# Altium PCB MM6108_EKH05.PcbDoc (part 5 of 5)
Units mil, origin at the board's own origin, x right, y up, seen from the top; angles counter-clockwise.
Board outline 6023.62 x 3425.2 mil, 4 copper layers (Top Layer, Ground Plane, Middle Layer, Bottom Layer), stack 76.15 mil thick; 212 components, 163 nets, 749 pads, 1477 vias.
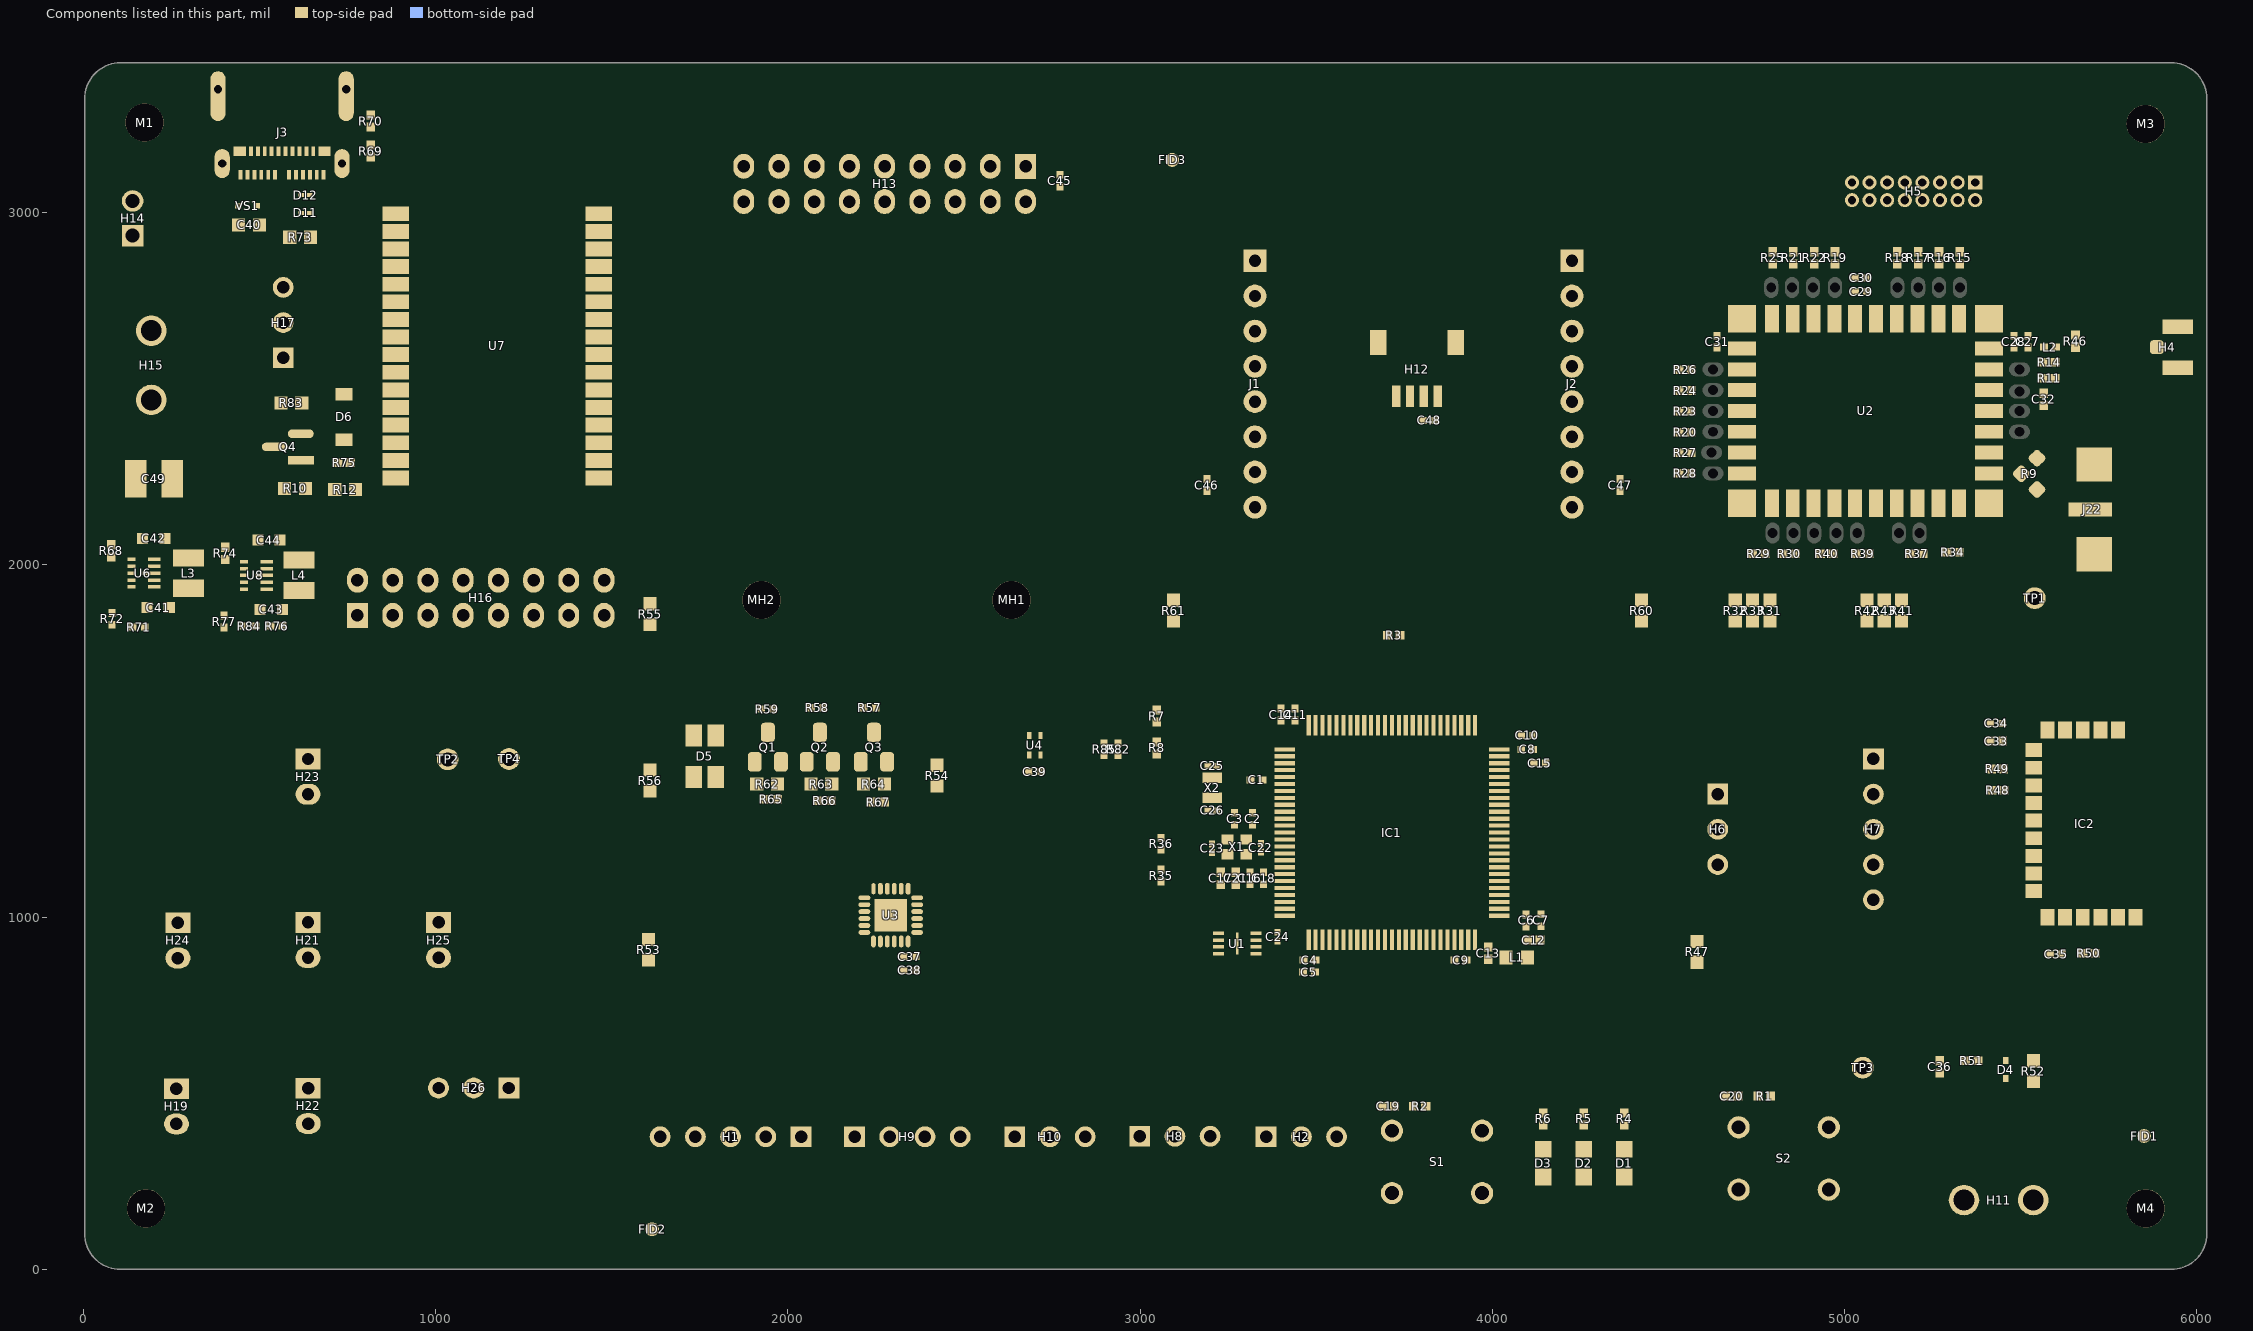
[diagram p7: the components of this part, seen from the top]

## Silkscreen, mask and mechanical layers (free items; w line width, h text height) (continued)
Fab Notes:
  lines w3.94: -58.84,-1054.17 -58.84,-602.42 1478.22,-602.42 1478.22,-1054.62 -58.39,-1054.62 ; 474.62,-1053.22 474.62,-602.42 ; 474.62,-964.17 1479.54,-964.17 ; 474.62,-874.07 1479.54,-874.07 ; 474.62,-783.52 1479.54,-783.52 ; 474.62,-692.97 1479.54,-692.97 ; 1182.3,-1055.61 1182.3,-965.06
  text "NOTES: UNLESS OTHERWISE SPECIFIED0" at -3357.21,2832.86 h60
  text "1. SPECIFICATIONS/TOLERANCES:" at -3357.21,2762.86 h60
  text "A. FABRICATE PER IPC-6012, CLASS 2, USING PROVIDED DATA FILES XXXXXXXX.ZIP" at -3357.21,2692.86 h60
  text "B. ALL SPECIFICATIONS USED SHALL BE PER THEIR LATEST REVISIONS." at -3357.21,2622.86 h60
  text "C. THE DIMENSIONS OF CIRCUIT FEATURES IN THE PROVIDED DATA MAY BE ADJUSTED" at -3357.21,2552.86 h60
  text "ONLY TO COMPENSATE FOR PROCESS TOLERANCES; ADDING, REMOVING OR RELOCATING" at -3357.21,2482.86 h60
  text "CIRCUIT FEATURES IS NOT ALLOWED" at -3357.21,2412.86 h60
  text "D. REMOVE ALL BURRS AND BREAK SHARP EDGES, .381 [.015] MAX RADIUS." at -3357.21,2342.86 h60
  text "E. PARENTHETICAL INFORMATION IS FOR REFERENCE ONLY." at -3357.21,2272.86 h60
  text "F. REPAIR OF PCB DEFECTS IS NOT PERMITTED." at -3357.21,2202.86 h60
  text "2. DIELECTRIC MATERIAL:" at -3357.25,2062.86 h60
  text "A. DIELECTRIC MATERIAL SHALL BE PER IPC-4101/99, /124, /126 OR /129 (RoHS COMPLIANT EPOXY-GLASS)" at -3357.21,1992.86 h60
  text "B. MINIMUM DIELECTRIC THICKNESS SHALL BE .051 [.002] FOR REFERENCED STACK-UP" at -3357.21,1922.86 h60
  text "DIMENSIONS OF.076 [.003] OR GREATER; IPC-6012 REQUIREMENTS SHALL OTHERWISE" at -3357.21,1852.86 h60
  text "APPLY. SINGLE-PLY CONSTRUCTION IS ALLOWED." at -3357.21,1782.86 h60
  text "C. SEE LAYER STACK-UP FOR REQUIRED COPPER WEIGHTS AND THE FINISHED PCB" at -3357.21,1712.86 h60
  text "THICKNESS. IF SPECIFIED, 1/3 OZ. STARTING FOIL MAY BE ACHIEVED BY 1/2 OZ. FOIL REDUCTION." at -3357.21,1642.86 h60
  text "D. FINISHED PCB THICKNESS SHALL BE MEASURED OVER LANDS AND/OR" at -3357.21,1572.86 h60
  text "CONDUCTORS NOT COVERED BY SOLDER MASK. IF SPECIFIED, 1/3 OZ. STARTING FOIL" at -3357.21,1502.86 h60
  text "MAY BE ACHIEVED BY 1/2 OZ. FOIL REDUCTION." at -3357.21,1432.86 h60
  text "3. DRILLING:" at -3357.21,1292.86 h60
  text "A. VIA DIAMETERS SHALL BE VERIFIED BEFORE PLATING; ALL OTHER HOLE" at -3357.21,1222.86 h60
  text "DIAMETERS ARE FINISHED DIMENSIONS." at -3357.21,1152.86 h60
  text "B. LAYER-TO-LAYER MISREGISTRATION SHALL BE .127 [.005] MAXIMUM." at -3357.21,1082.86 h60
  text "4. SOLDER MASK:" at -3357.21,942.86 h60
  text "A. APPLY LPI SOLDER MASK OVER BARE COPPER USING PROVIDED DATA." at -3357.21,872.86 h60
  text "B. SOLDER MASK SHALL BE PER IPC-SM-840, CLASS T, COLOR PURPLE." at -3357.21,802.86 h60
  text "C. THE DIMENSIONS OF SOLDER MASK-DEFINED PADS ON PLANES AND/OR WIDE" at -3357.21,732.86 h60
  text "CONDUCTORS SHALL NOT BE MODIFIED." at -3357.21,662.86 h60
  text "5. SILKSCREEN/MARKING:" at -3357.21,522.86 h60
  text "A. SILKSCREEN PCB PER PROVIDED DATA USING PERMANENT, NON-CONDUCTIVE" at -3357.21,452.86 h60
  text "INK, COLOR WHITE." at -3357.21,382.86 h60
  text "B. SUPPLIER ID AND TRACEABILITY INFORMATION SHALL NOT / BE APPLIED ON ANY PART OF THE PCB" at -3356.19,209.11 h60
  text "C. INK SHALL NOT BE APPLIED TO ANY SOLDERABLE SURFACE." at -3357.21,133.49 h60
  text "USING PROVIDED DATA." at -3357.21,63.49 h60
  text "6. ELECTRICAL TEST:" at -3357.21,-76.51 h60
  text "A. DESIGN VERIFICATION SHALL BE DONE PRIOR TO PCB FABRICATION USING" at -3357.21,-146.51 h60
  text "GERBER DATA AND AN IPC-D-356 NETLIST." at -3357.21,-216.51 h60
  text "B. ALL PCBS SHALL BE 100% ELECTRICALLY TESTED FOR OPENS AND SHORTS" at -3357.21,-286.51 h60
  text "C. APPLY TEST STAMP IN NON-LEGEND AREA ON SECONDARY SIDE OF PCB." at -3357.21,-356.51 h60
  text "7. FINAL FINISH:" at -3357.21,-491.51 h60
  text "A. FINAL FINISH SHALL BE ELECTROLESS NICKEL/IMMERSION GOLD (ENIG) PER IPC-4552." at -3357.21,-565.54 h60
  text "Project:" at 492.34,-665.41 h60
  text "EKH05" at 753.17,-670.33 h80
  text "8. IMPEDANCE:" at -3360.68,-673.63 h60
  text "A. IMPEDANCE TOLERANCE SHALL BE +/- 10%." at -3360.68,-743.63 h60
  text "Company:" at 492.34,-755.96 h60
  text "Morse Micro" at 753.22,-760.88 h80
  text "B. SEE LAYER STACK-UP FOR IMPEDANCE REQUIREMENTS." at -3360.68,-813.63 h60
  text "Drawn By:" at 492.34,-846.51 h60
  text ".DrawnBy" at 753.17,-853.4 h80
  text "9. IF PANELIZATION SPECIFICATIONS ARE PROVIDED, THE PCBS SHALL BE DELIVERED IN PANEL" at -3347.21,-936.51 h60
  text "FORM. HOWEVER, THESE SPECIFICATIONS MAY BE REPLACED BY SUPPLIER PREFERRED" at -3347.21,-1006.51 h60
  text "Date:" at 492.34,-1027.06 h60
  text "Rev:" at 1210.84,-1031 h60
  text ".Print_Date" at 753.17,-1037.89 h80
  text ".Rev" at 1338.8,-1038.76 h80
  text "(SPECIFICATIONS AS APPROVED)." at -3347.21,-1076.51 h60
Board:
  lines w3.94: 2759.75,1393.68 cw(c2740.06,1393.68) 2740.06,1374 2661.51,1374.04 cw(c2661.51,1393.72) 2641.83,1393.72 2641.66,1440.82 2641.66,1530.27 cw(c2656.67,1530.32) 2656.62,1545.33 ccw(c2656.24,1556.72) 2667.64,1556.72 2667.64,1562.45 ccw(c2656.24,1562.45) 2656.62,1573.84 2617.89,1573.83 ccw(c2617.89,1558.23) 2602.29,1558.23 2602.29,1354.38 ccw(c2621.98,1354.38) 2621.98,1334.69 2779.45,1334.68 ; 2759.77,1393.68 2759.77,1440.82 2759.77,1530.27 ccw(c2744.76,1530.32) 2744.8,1545.33 cw(c2745.18,1556.72) 2733.78,1556.72 2733.79,1566.58 cw(c2740.92,1566.58) 2740.68,1573.7 2779.45,1573.84 ; 2779.45,1334.65 ccw(c2779.45,1354.33) 2799.14,1354.33 2799.14,1419.02 2799.14,1554.11 ccw(c2779.45,1554.11) 2779.45,1573.8
  lines w4: 5773.62,2012.13 5773.62,2292.83 5773.62,2296.75 ; 6027.56,2017.13 6027.56,100 6027.56,90.15 6023.72,70.83 6016.18,52.63 6005.23,36.25 5991.31,22.32 5974.93,11.38 5956.73,3.84 5937.41,0 103.94,0 94.09,0 74.77,3.84 56.57,11.38 40.19,22.32 26.26,36.25 15.32,52.63 7.78,70.83 3.94,90.15 3.94,100 3.94,275.59 3.94,3188.98 3.94,3325.2 3.94,3335.05 7.78,3354.37 15.32,3372.56 26.26,3388.94 40.19,3402.87 56.57,3413.82 74.77,3421.35 94.09,3425.2 103.94,3425.2 5937.41,3425.2 5956.73,3421.35 5974.93,3413.82 5991.31,3402.87 6005.23,3388.94 6016.18,3372.56 6023.72,3354.37 6027.56,3335.05 6027.56,3325.2 6027.56,2297.84 ; 2621.98,1334.68 2779.45,1334.68 2779.45,1334.65 2783.37,1334.65 2790.6,1337.64 2796.14,1343.18 2799.14,1350.42 2799.14,1354.33 2799.14,1551.21 2799.43,1555.42 2796.75,1563.42 2791.21,1569.79 2783.66,1573.55 2779.45,1573.84 ; 2621.98,1334.68 2621.98,1334.69 ; 2621.98,1334.69 2618.06,1334.69 2610.82,1337.69 2605.29,1343.23 2602.29,1350.46 2602.29,1354.38 2602.29,1558.22 2602.29,1561.33 2604.66,1567.07 2609.06,1571.46 2614.8,1573.84 2617.9,1573.84 2621.97,1573.84 2656.62,1573.84 ; 2656.62,1545.33 2659.09,1545.41 2663.5,1547.6 2666.63,1551.41 2667.89,1556.17 2667.49,1558.6 ; 2656.62,1545.33 2656.62,1545.33 ; 2656.62,1545.33 2653.7,1545.03 2648.29,1542.77 2644.16,1538.62 2641.94,1533.2 2641.66,1530.27 2641.66,1440.82 2641.83,1393.72 2642.2,1389.88 2645.14,1382.79 2650.57,1377.35 2657.67,1374.41 2661.51,1374.04 2740.06,1374 2743.9,1374.37 2751,1377.31 2756.43,1382.75 2759.37,1389.84 2759.75,1393.68 2759.77,1393.68 2759.77,1530.27 ; 2656.62,1573.84 2656.62,1573.84 ; 2656.62,1573.84 2659.26,1573.49 2663.83,1570.75 2666.92,1566.42 2668.02,1561.21 2667.49,1558.6 ; 2667.49,1558.6 2667.49,1558.6 ; 2744.8,1545.33 2747.73,1545.03 2753.13,1542.77 2757.26,1538.62 2759.49,1533.2 2759.77,1530.27 ; 2744.8,1545.33 2744.8,1545.33 ; 2744.8,1545.33 2742.58,1545.4 2738.53,1547.21 2735.45,1550.4 2733.79,1554.51 2733.79,1556.73 2733.79,1566.58 2733.79,1568.02 2734.9,1570.69 2736.94,1572.73 2739.61,1573.84 2741.05,1573.84 2779.45,1573.84 ; 2759.77,1530.27 2759.77,1530.27 ; 2779.45,1573.84 2779.45,1573.84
